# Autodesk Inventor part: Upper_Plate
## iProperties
Shininess: 15.0
Length Units: 11272
Angle Units: 11279
Time Units: 11290
Mass Units: 11283
Length Display Precision: 2
Angle Display Precision: 1
Created: 1999-05
Part Number: Upper_Plate
Document SubType Name: Modeling
Designer: Administrator
Density: 7.86 g/cm^3
Density: 7.86
Volumn: 11.910644871161018
Area: 90.04134983224549
PropertySet Name: Model Information
Control State: 0
Master: False
Checked Out: False
Author: Administrator
